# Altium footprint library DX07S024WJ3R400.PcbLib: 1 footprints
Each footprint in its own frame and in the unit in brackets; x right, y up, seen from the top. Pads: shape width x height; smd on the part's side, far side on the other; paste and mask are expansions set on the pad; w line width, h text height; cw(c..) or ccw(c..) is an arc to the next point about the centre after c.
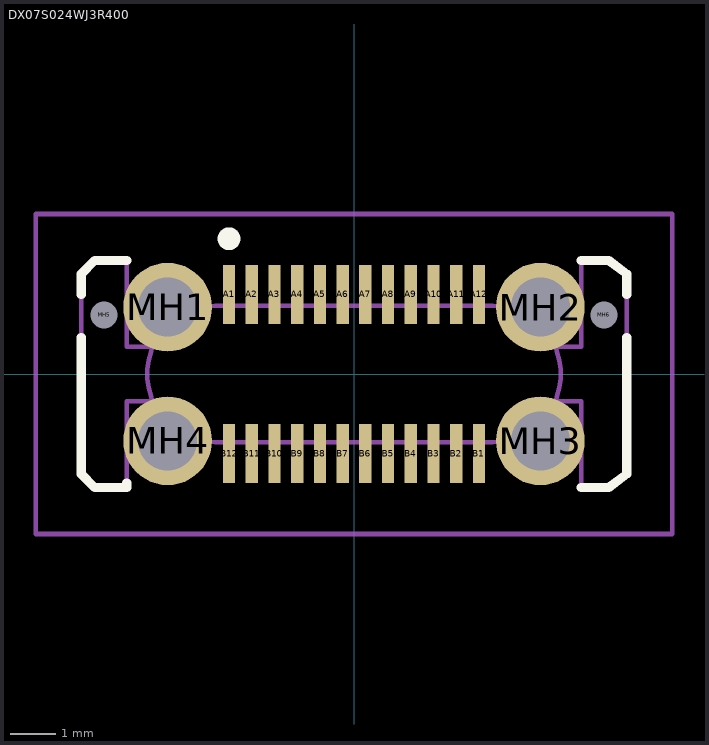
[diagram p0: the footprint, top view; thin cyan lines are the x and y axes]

## DX07S024WJ3R400 [mm]
pads (30):
  rect 0.27x1.3 smd: A1(-2.75,1.75) A2(-2.25,1.75) A3(-1.75,1.75) A4(-1.25,1.75) A5(-0.75,1.75) A6(-0.25,1.75) A7(0.25,1.75) A8(0.75,1.75) A9(1.25,1.75) A10(1.75,1.75) A11(2.25,1.75) A12(2.75,1.75) B1(2.75,-1.75) B2(2.25,-1.75) B3(1.75,-1.75) B4(1.25,-1.75) B5(0.75,-1.75) B6(0.25,-1.75) B7(-0.25,-1.75) B8(-0.75,-1.75) B9(-1.25,-1.75) B10(-1.75,-1.75) B11(-2.25,-1.75) B12(-2.75,-1.75)
  round 1.95 hole 1.3: MH1(-4.1,1.47) MH2(4.1,1.47) MH3(4.1,-1.47) MH4(-4.1,-1.47)
  round 0.3 hole 0.6 unplated: MH5(-5.5,1.3) MH6(5.5,1.3)
Top Overlay:
  lines w0.2: -6,0.8 -6,-2.2 -5.7,-2.5 -5,-2.5 -5,-2.4 ; -6,1.75 -6,2.2 -5.7,2.5 -5,2.5 ; 5,-2.5 5.6,-2.5 6,-2.2 6,0.8 ; 5,2.5 5.6,2.5 6,2.2 6,1.75
  lines w0.25: -2.75,2.85 -2.75,2.85 ; -2.75,2.85 ccw(c-2.75,2.975) -2.75,3.1 ; -2.75,2.85 cw(c-2.75,2.975) -2.75,3.1 ; -2.75,3.1 -2.75,3.1
Mechanical 15:
  lines w0.1: -4.4,-0.6 -5,-0.6 -5,-2.5 -5.7,-2.5 -6,-2.2 -6,2.2 -5.7,2.5 -5,2.5 -5,0.6 -4.4,0.6 ; 4.4,-0.6 5,-0.6 5,-2.5 5.6,-2.5 6,-2.2 6,2.2 5.6,2.5 5,2.5 5,0.6 4.4,0.6 ; -3.05,-1.5 0,-1.5 3.05,-1.5 ccw(c3.05,0) 3.05,1.5 ; -3.05,-1.5 -3.05,-1.5 ; -3.05,-1.5 cw(c-3.05,0) -3.05,1.5 3.05,1.5 ; 3.05,1.5 3.05,1.5
Mechanical 20:
  lines w0.1: -7,-3.52 7,-3.52 7,3.52 -7,3.52 -7,-3.52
